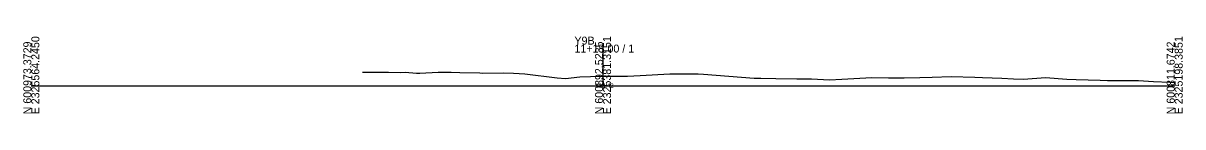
# Model space of a CAD drawing. Extents: x -26 to 3203, y 990 to 2017.
# Drawn here: x 1397.2 to 1802.8, y 1490.3 to 1517.4 of the extents above; entities that cross this region are included whole.
import ezdxf

# ---------------------------------------------------------------- set-up
doc = ezdxf.new("R2010")
doc.units = 0
for name, color, linetype in [('Exist Cross Section Cell', 7, 'Continuous'), ('Exist XS Center Line Elevation Label', 7, 'Continuous'), ('Exist XS Ground Line', 7, 'Continuous')]:
    doc.layers.add(name, color=color, linetype=linetype)

msp = doc.modelspace()

# ---------------------------------------------------------------- linework, layer by layer
at = {"layer": 'Exist Cross Section Cell'}
for p, q in [((1600, 1500), (1600, 1514.53)), ((1400, 1500), (1600, 1500)), ((1600, 1500), (1800, 1500))]:
    msp.add_line(p, q, dxfattribs=at)
at = {"layer": 'Exist XS Ground Line'}
msp.add_lwpolyline([(1515.89, 1504.81), (1522.42, 1504.84), (1524.96, 1504.82), (1529.06, 1504.73), (1530.75, 1504.82), (1534.76, 1504.47), (1535.89, 1504.46), (1542.34, 1504.81), (1546.83, 1504.82), (1549.93, 1504.76), (1556.93, 1504.56), (1557.76, 1504.54), (1565.09, 1504.64), (1568.7, 1504.51), (1572.67, 1504.27), (1584.02, 1502.87), (1586.93, 1502.66), (1591.9, 1503.18), (1599.35, 1503.41), (1600, 1503.42), (1600.62, 1503.42), (1603.17, 1503.41), (1608.59, 1503.39), (1613, 1503.62), (1623.37, 1504.26), (1625.76, 1504.26), (1631.16, 1504.23), (1633.34, 1504.2), (1635.11, 1504.13), (1652.83, 1502.73), (1655.18, 1502.7), (1660.52, 1502.66), (1667.77, 1502.53), (1669.51, 1502.49), (1672.91, 1502.48), (1679.18, 1502.18), (1683.53, 1502.41), (1694, 1502.96), (1699.91, 1502.81), (1705.38, 1502.86), (1710.84, 1503.02), (1715.17, 1503.12), (1721.78, 1503.28), (1730.12, 1503.1), (1732.71, 1503.01), (1739.5, 1502.69), (1743.65, 1502.52), (1747.08, 1502.41), (1754.86, 1502.96), (1762.25, 1502.35), (1765.52, 1502.27), (1773.96, 1502.05), (1776.45, 1501.95), (1779.6, 1501.93), (1787.39, 1501.86), (1792.58, 1501.56), (1798.32, 1501.27), (1800, 1501.26)], dxfattribs=at)

# ---------------------------------------------------------------- texts
at = {"layer": 'Exist Cross Section Cell'}
for s, p in [('E 2325564.2450', (1402.8, 1490)), ('E 2325381.3151', (1602.8, 1490)), ('E 2325198.3851', (1802.8, 1490)), ('N 600973.3729', (1400, 1490)), ('N 600892.5235', (1600, 1490)), ('N 600811.6742', (1800, 1490))]:
    msp.add_text(s, height=2.8, rotation=90, dxfattribs=at).set_placement(p)
for s, p in [('Y9B', (1590, 1514.53)), ('11+15.00 / 1', (1590, 1511.73))]:
    msp.add_text(s, height=2.8, dxfattribs=at).set_placement(p)
at = {"layer": 'Exist XS Center Line Elevation Label'}
msp.add_text('118.42', height=1.5, dxfattribs=at).set_placement((1597.37, 1499.42))

doc.saveas('drawing.dxf')
